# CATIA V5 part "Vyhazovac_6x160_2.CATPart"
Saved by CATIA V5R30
Part number: Vyhazovac_6x160_2
Nomenclature: E1710/6x160
Description: MEUSBURGER
Property "Material": "1.221"
Publications: "__DrillHole", "Base"
Bounding box of the stored display mesh (mm): x -5.992 to 5.992, y -5.992 to 5.992, z 0 to 152
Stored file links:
  E:\Bakalarka\Model\Forma_v7\Vyhazovac_6x160_2.CATPart
  E:\dev\MoldDesign\intel_a\startup\components\MoldCatalog\Ejector\Meusburger\Ejector_E1710\TableE1710.txt
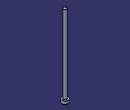
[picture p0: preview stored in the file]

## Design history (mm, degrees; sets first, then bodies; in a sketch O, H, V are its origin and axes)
Parameters
  Ref = "E1710/6x160" {design table}
  D1 = 6 mm {design table}
  D3 = 12 mm {design table}
  L = 160 mm {design table}
  L3 = 5 mm {design table}
  R = 0.5 mm {design table}
  k_d3 = 13 mm {design table}
  k_d1 = 6.2 mm {design table}
  k_F = 0.5 mm {design table}
  kl = 17 mm {design table}
  Mat = "1.221" {design table}
  HeatTreat = "ISO6751" {design table}
  Offset_Parting = 10 mm
  Anti_Rotation = "Normal"
  Anti_Rotation_D = 3.5 mm
  Anti_Rotation_D_Icut = 3.5 mm
  Add_Length_L = 1.8377 mm
  Add_Length_D3 = 0 mm
  SupplierRef = "Meusburger 2017"
  BmpRef = "F_MldEjectorD1"
  DrillHole_Length = 225 mm
  ValidationTest = false
  Anti_Rotation_D_min = 3.5 mm {= OffSet_D1 /2}
  Anti_Rotation_D_max = 5.925 mm {= D3/2-0.075mm}
  Anti_Rotation_D_ref = 3.5 mm {= Anti_Rotation_D}
  Anti_Rotation_D_Icut_ref = 3.5 mm {= Anti_Rotation_D_Icut}
  Anti_Rotation_Ref_Icut = 2.3246 mm
  Offset_L = 20 mm
  D = 6 mm {= D1}
  OffSet_D1 = 7 mm {= D1+2*R}
  OffSet_D3 = 13 mm {= D3+1mm}
  XG_Split = 92 mm
  YG_Split = -31 mm
  ZG_Split = -198 mm
  DirX_Split = 0 mm
  DirY_Split = 0 mm
  DirZ_Split = 1 mm
Set1 "BaseBody"
  Point1 "Base": (0, 0, 0)
  Plane1: type Offset, RefPlane xy-plane, Offset 225 {= DrillHole_Length}, reversed
  Sketch1 "Sketch.2" on xy-plane, origin (0, 0, 0), H (1, 0, 0), V (0, 1, 0)
    point P1 (-0.46, 1.1623)
    point P2 (0.46, 1.1623)
    construction line L1 (-0.46, 1.1623) -> (0.46, 1.1623)
    point P3 (0.46, -1.1623)
    line L2 (0.46, -1.1623) -> (0.46, 1.1623)
    point P4 (-0.46, -1.1623)
    construction line L3 (0.46, -1.1623) -> (-0.46, -1.1623)
    line L4 (-0.46, 1.1623) -> (-0.46, -1.1623)
    point P5 (-0.21, 1.1623)
    arc A1 centre (-0.21, 1.1623) radius 0.25 from (-0.21, 1.4123) to (-0.46, 1.1623) ccw
    point P7 (0.21, 1.1623)
    point P8 (0.21, 1.4123)
    arc A2 centre (0.21, 1.1623) radius 0.25 from (0.46, 1.1623) to (0.21, 1.4123) ccw
    line L5 (-0.21, 1.4123) -> (0.21, 1.4123)
    point P9 (-0.46, -1.1623)
    arc A3 centre (-0.21, -1.1623) radius 0.25 from (-0.46, -1.1623) to (-0.21, -1.4123) ccw
    point P11 (0.21, -1.4123)
    line L6 (-0.21, -1.4123) -> (0.21, -1.4123)
    point P12 (0.46, -1.1623)
    arc A4 centre (0.21, -1.1623) radius 0.25 from (0.21, -1.4123) to (0.46, -1.1623) ccw
    point P14 (-0.46, 1.1623)
    point P15 (-0.46, -1.1623)
    point P16 (0.46, 1.1623)
    point P17 (0.46, -1.1623)
    reference projected circle E1 centre (0, 0) radius 1.25 from edge [face of Shaft1 from Sketch2.L3 | face of Shaft1 from Sketch2.L4]
    reference projected circle E2 centre (0, 0) radius 1.25 from edge [face of Shaft1 from Sketch2.L3 | face of Shaft1 from Sketch2.L4]
    reference projected circle E3 centre (0, 0) radius 1.25 from edge [face of Shaft1 from Sketch2.L3 | face of Shaft1 from Sketch2.L4]
    reference projected circle E4 centre (0, 0) radius 1.25 from edge [face of Shaft1 from Sketch2.L3 | face of Shaft1 from Sketch2.L4]
    point P18 (-0.46, -1.1623)
    point P19 (-0.21, -1.4123)
    point P20 (0.21, -1.4123)
    point P21 (0.46, -1.1623)
    point P22 (-0.21, -1.4123)
    point P23 (0.21, -1.4123)
    distance P14 P15 = 2.3246 (reference)
    distance P16 P17 = 2.3246 (reference)
    distance L1 P14 = 0 (reference)
    radius A1 = 3
    distance L4 V = 3.51
    distance L2 V = 5.935
    distance L5 L6 = 12
    horizontal: L1 H, L3 H, L5 H
    vertical: L2 V, L4 V
    coincidence: P5 L1, P7 L1, P3 P12, P14 L4, P15 L4, P16 L2, P17 L2, P14 E1, P15 E2, P16 E3, P17 E4, P3 P21, P4 P18, P20 P23, P19 P22
    tangency: A1 L4, A2 L2, A2 L5, A1 L5
    symmetry: P1 P9 H, A1 A3 H, P8 P11 H, L5 L6 H, P2 P12 H, A2 A4 H
  DatumSurface1
Body1 "PartBody" (main body)
  Sketch2 "Sketch.1" on zx-plane, origin (0, 0, 0), H (-1, 0, 0), V (0, 0, 1)
    point P1 (0, 160)
    line L1 (3, 160) -> (0, 160)
    line L2 (3, 5) -> (3, 160)
    line L3 (6, 5) -> (3, 5)
    line L4 (6, 0) -> (6, 5)
    point P5 (0, 0)
    line L5 (0, 0) -> (6, 0)
    point P6 (0, 160)
    axis line L6 (0, 160) -> (0, 0)
    point P7 (0, 0)
    point P8 (3, 5)
    point P9 (3, 5)
    line L7 (0, 160) -> (0, 0)
    distance L5 L3 = 5 {= L3}
    distance L5 L1 = 160 {= L}
    distance L2 L6 = 3 {= D1 /2}
    distance L4 L6 = 6 {= D3 /2}
    coincidence: L6 P5, P1 L6, L5 H, L6 V, P7 O, P6 P1, P8 P9
    vertical: L2 V, L7 V
    horizontal: L1 H
  Shaft1 "Shaft.1": profile Sketch2, axis Sketch2.L6, angle 360
  Pocket1 "Pocket.1": profile Sketch1, direction (0, 0, 1), length 6, outer side, deactivated
  Pocket2 "Pocket.2": profile Sketch1, direction (0, 0, 1), length 6, outer side, deactivated
  Fillet1: radius 0.5 {= R}, on edge [face of Shaft1 from Sketch2.L2 | face of Shaft1 from Sketch2.L3]
  Pocket3: profile face of Shaft1 from Sketch2.L1, direction along face of Shaft1 from Sketch2.L1, up to face of DatumSurface1
Body2 "__DrillHole"
  Sketch3 "Sketch.3" on face of Shaft1, origin (0, 0, 0), H (1, 0, 0), V (0, -1, 0)
    point P1 (0, 0)
    reference projected point E1 (0, 0) from Point1
    coincidence: E1 P1
  Hole1 "Hole.1": placed by Sketch3, at (0, 0, 0) direction (0, 0, 1), diameter 7 {= OffSet_D1}, depth 140 {= L-Offset_L}
  Sketch4 "Sketch.4" on face of Shaft1, origin (0, 0, 0), H (1, 0, 0), V (0, -1, 0)
    point P1 (0, 0)
    reference projected point E1 (0, 0) from Point1
    coincidence: E1 P1
  Hole2 "Hole.2": placed by Sketch4, at (0, 0, 0) direction (0, 0, 1), diameter 6 {= D1}, depth 160 {= L}
  Sketch5 "Sketch.5" on face of Shaft1 from Sketch2.L3, origin (0, 0, 5), H (1, 0, 0), V (0, 1, 0)
    point P1 (0, 0)
    reference projected point E1 (0, 0) from Point1
    coincidence: E1 P1
  Hole3 "Hole.3": placed by Sketch5, at (0, 0, 5) direction (0, 0, -1), diameter 13 {= OffSet_D3}, depth 230 {= L3 +DrillHole_Length}
  Chamfer1: length 0.5 {= k_F}, angle 45, on edge [face of Hole1 | face of Hole3]
  Body3 "__Body.1"
    Pocket4 "Pocket.3": profile Sketch1, direction (0, 0, -1), length 225, opposite side length 5, deactivated
  Assemble1: tool Body3
  Chamfer2: length 0.5 {= k_F}, angle 45, on edge [start face of Pocket4 | face of Hole1], deactivated
  Body4 "__Body.2"
    Pocket5 "Pocket.4": profile Sketch1, direction (0, 0, -1), length 225, opposite side length 5, deactivated
  Assemble2: tool Body4
  Chamfer3: length 0.5 {= k_F}, angle 45, on edge [start face of Pocket5 | face of Hole1], deactivated
Relations
  design table "TableE1710", configuration 254, drives Ref, D1, D3, L, L3, R, k_d3, k_d1, k_F, kl, Mat, HeatTreat
  Offset_L = 20mm (deactivated)
  rule "Cut_Head_rule":
    let sketch_cut (length)
    let PartBody_Pocket_Sketch (Boolean)
    let I_PartBody_Pocket (Boolean)
    let D_PartBody_Pocket (Boolean)
    let N_DrillHole_Hole (Boolean)
    let N_DrillHole_Hole_Sketch (Boolean)
    let I_DrillHole_Pocket (Boolean)
    let D_DrillHole_Pocket (Boolean)
    /* --------------------------------------------------------------------------------------*/
    if Anti_Rotation =="Normal"
    {
    	sketch_cut=Anti_Rotation_D_max
    	PartBody_Pocket_Sketch = false
    	I_PartBody_Pocket = false
    	D_PartBody_Pocket = false
    	N_DrillHole_Hole = true
    	N_DrillHole_Hole_Sketch = true
    	I_DrillHole_Pocket = false
    	D_DrillHole_Pocket = false
    	Chamfer1.Activity= true
    	Chamfer2.Activity= false
    	Chamfer3.Activity= false
    }
    if Anti_Rotation == "I_Cut"
    {
    	sketch_cut=Anti_Rotation_D_Icut_ref
    	PartBody_Pocket_Sketch = true
    	I_PartBody_Pocket = true
    	D_PartBody_Pocket = false
    	N_DrillHole_Hole = false
    	N_DrillHole_Hole_Sketch = false
    	I_DrillHole_Pocket = true
    	D_DrillHole_Pocket = false
    	Chamfer1.Activity= false
    	Chamfer2.Activity= true
    	Chamfer3.Activity= false
    }
    if Anti_Rotation =="D_Cut"
    {
    	sketch_cut=Anti_Rotation_D_max
    	PartBody_Pocket_Sketch = true
    	I_PartBody_Pocket = false
    	D_PartBody_Pocket = true
    	N_DrillHole_Hole = false
    	N_DrillHole_Hole_Sketch = false
    	I_DrillHole_Pocket = false
    	D_DrillHole_Pocket = true
    	Chamfer1.Activity= false
    	Chamfer2.Activity= false
    	Chamfer3.Activity= true
    }
    /* --------------------------------------------------------------------------------------*/
    Sketch1.distance(L2 V) = sketch_cut+0.01mm
    Sketch1.distance(L4 V) =Anti_Rotation_D_ref+0.01mm
    Sketch1.radius(A1) =D/2
    Pocket4.FirstLimit.Depth = DrillHole_Length
    Pocket5.FirstLimit.Depth = DrillHole_Length
    Pocket1.FirstLimit.Depth = L3+1mm
    Pocket2.FirstLimit.Depth = L3+1mm
    Pocket4.SecondLimit.Depth = L3
    Pocket5.SecondLimit.Depth =L3
    Pocket1.Activity = I_PartBody_Pocket
    Pocket2.Activity = D_PartBody_Pocket
    Sketch1.Activity =PartBody_Pocket_Sketch
    Hole3.Activity= N_DrillHole_Hole
    Sketch5.Activity = N_DrillHole_Hole_Sketch
    Pocket4.Activity = I_DrillHole_Pocket
    Pocket5.Activity  = D_DrillHole_Pocket
  rule "Anti_Rotation_Icut_constrain":
    let Ref1(length)
    let Ref2(length)
    let Ref3(length)
    let Diam1(length)
    let Diam2(length)
    let Add_Length_Lmin (length)
    Ref1=Sketch1.distance(P14 P15)
    Ref2=Sketch1.distance(P16 P17)
    Diam1=D
    Diam2=D3
    /* --------------------------------------------------------------------*/
    if Ref1 >Ref2
    	Anti_Rotation_Ref_Icut = Ref1
    else
    	Anti_Rotation_Ref_Icut  =Ref2
    Add_Length_D3 .InferiorRange=Anti_Rotation_Ref_Icut /2+Diam1/2 -Diam2/2
    if Add_Length_D3 .InferiorRange<0mm
    	Add_Length_D3 .InferiorRange=0mm
    if ValidationTest == "true"
    	Ref3   = 2*Add_Length_L +Anti_Rotation_Ref_Icut  +2*Diam1/2
    else
    	Ref3  =Diam2+2*Add_Length_D3
    if Ref3 <Diam2
    {
    	Ref3 =Diam2
    }
    /* --------------------------------------------------------------------*/
    Sketch1.distance(L5 L6) = Ref3
    Add_Length_L .InferiorRange=Diam2/2-Anti_Rotation_Ref_Icut/2-Diam1/2
    Add_Length_Lmin=Diam2/2-Anti_Rotation_Ref_Icut/2-Diam1/2
    if Add_Length_Lmin<0mm
    	Add_Length_L .InferiorRange=0mm
    else
    	Add_Length_L .InferiorRange=Add_Length_Lmin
